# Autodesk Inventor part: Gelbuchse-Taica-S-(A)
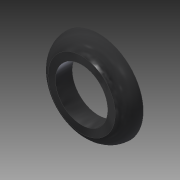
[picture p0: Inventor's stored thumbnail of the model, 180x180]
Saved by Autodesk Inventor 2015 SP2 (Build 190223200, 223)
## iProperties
Created: 2014-11
Part Number: Gelbuchse-Taica-S-(A)
Material: Gummi, Silikon
Document SubType Name: Modeling
Designer: Hübner
Density: 1 g/cm^3
Appearance: Gummi - schwarz - Version 1.1
Author: Hübner
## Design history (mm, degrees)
sketch "Skizze1"
  geometry: C1 r 3.5 at (0, 0); C2 r 6 at (0, 0); 1 further point
  constraints: 2 centre point, 2 coincident
  dimensions: "d0" = 7 diameter of C1; "d1" = 12 diameter of C2
extrude "Extrusion2" new body sketch "Skizze1" distance "d4" = 2.25; taper "d5" = 0 deg
sketch "Skizze2"
  geometry: L1 (0, 6)-(0, -6) reference; L2 (0, 6)-(-2.25, 6) reference; L3 (-2.25, 6)-(-2.25, -6) reference; L4 (-2.972, 0)-(0.495, 0) reference; A1 r 2.437 centre (0, 3.563) between (0, 6) and (-2.25, 4.5); 1 further point
  constraints: 2 point on circle, 2 point on line, 1 centre point, 1 end point
  dimensions: "d19" = 4.5 distance from line of L4 A1.end
revolve "Umdrehung1" sketch "Skizze2" stored, may be unused: angle "d18" = 90 deg
node "Volumenkörper1"
